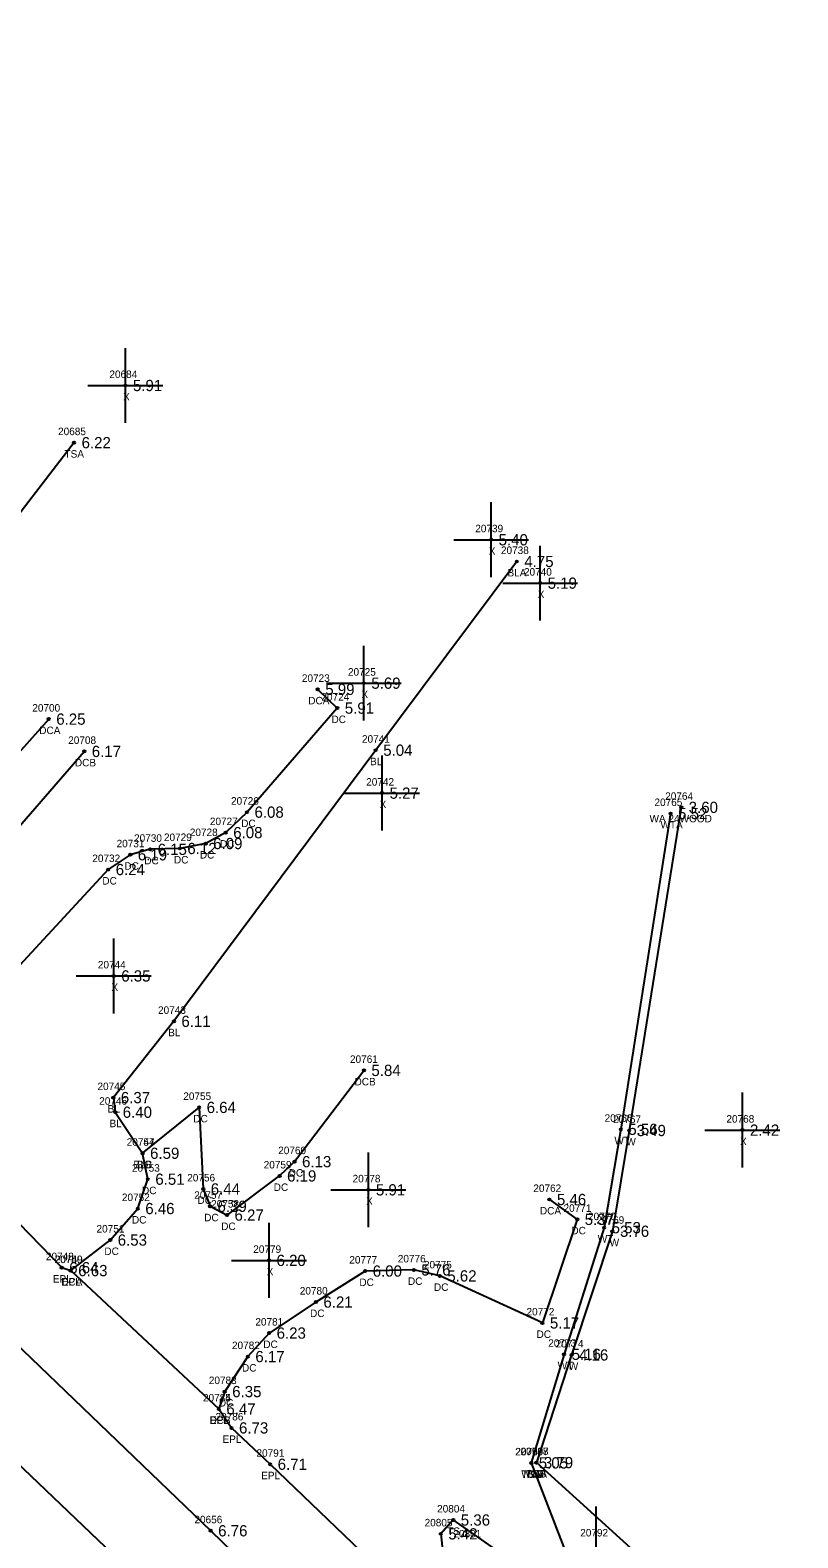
# Model space of a CAD drawing. Extents: x 2608745 to 2610333, y 641917 to 643463.
# Drawn here: x 2609231.6 to 2609334.1, y 642947.8 to 643149.1 of the extents above; entities that cross this region are included whole.
import ezdxf

# ---------------------------------------------------------------- set-up
doc = ezdxf.new("R2010")
doc.units = 0
for name, color, linetype in [('RD_DTM_BkLn1', 7, 'Continuous'), ('RD_DTM_BkLn2', 7, 'Continuous'), ('RD_DTM_BkLn_txCode', 7, 'Continuous'), ('RD_EX_BldgApp', 7, 'Continuous'), ('RD_EX_Conc', 7, 'Continuous'), ('RD_EX_Conc_txCode', 7, 'Continuous'), ('RD_EX_H2O_txCode', 7, 'Continuous'), ('RD_EX_Misc', 7, 'Continuous'), ('RD_EX_Misc_txCode', 7, 'Continuous'), ('RD_EX_Road', 7, 'Continuous'), ('RD_EX_Road_txCode', 7, 'Continuous'), ('RD_EX_TX_Conc_ELEV', 7, 'Continuous'), ('RD_EX_TX_Misc_ELEV', 7, 'Continuous'), ('RD_EX_TX_Road_ELEV', 7, 'Continuous'), ('RD_HC_Survey_ELEV', 7, 'Continuous'), ('RD_HC_Survey_txCode', 7, 'Continuous'), ('RD_SMD_Locator', 7, 'Continuous')]:
    doc.layers.add(name, color=color, linetype=linetype)

msp = doc.modelspace()

# ---------------------------------------------------------------- linework, layer by layer
at = {"layer": 'RD_DTM_BkLn1'}
for points in [[(2608814.73, 643373.65), (2608890.45, 643300.26), (2608962.19, 643231.31), (2609034.91, 643161.19), (2609108.48, 643089.9), (2609179.19, 643022.29), (2609255.71, 642948.78), (2609335.19, 642871.73), (2609410.7, 642798.48), (2609491.67, 642719.95), (2609518.07, 642695.15)], [(2609296.57, 643078.16), (2609277.74, 643052.97), (2609250.8, 643016.78), (2609242.72, 643006.6), (2609242.97, 643004.65), (2609246.62, 642999.17)]]:
    msp.add_lwpolyline(points, dxfattribs=at)
at = {"layer": 'RD_DTM_BkLn2'}
for points in [[(2609237.48, 643094.02), (2609220.03, 643071.4), (2609211.12, 643054.65), (2609205.92, 643044.31), (2609194.28, 643037.36), (2609184.97, 643038.02), (2609177.99, 643040.62)], [(2609317.09, 643044.52), (2609310.45, 643002.37), (2609308.22, 642989.24), (2609302.88, 642972.34), (2609298.5, 642957.84)], [(2609298.5, 642957.84), (2609303.58, 642944.57), (2609301.78, 642940.67), (2609288.09, 642950.22), (2609286.42, 642948.37), (2609286.98, 642943.32), (2609297.07, 642935.45), (2609305.3, 642928.41), (2609313.77, 642918.5), (2609346.23, 642882.3), (2609422.21, 642809.45), (2609480.56, 642755.4), (2609506.75, 642733.83), (2609516.79, 642724.84), (2609528.1, 642713.09), (2609531.25, 642709.73), (2609532.97, 642706.82)], [(2609299.18, 642957.88), (2609318.45, 642940.41), (2609325.58, 642932.79), (2609321.98, 642922.91), (2609316.71, 642922.45), (2609350.68, 642886.23), (2609426.26, 642812.92), (2609486.18, 642762.85), (2609511.6, 642739.79), (2609523.11, 642729.83), (2609533.96, 642717.19), (2609534.91, 642710.27), (2609532.97, 642706.82)]]:
    msp.add_lwpolyline(points, dxfattribs=at)
at = {"layer": 'RD_EX_BldgApp'}
msp.add_lwpolyline([(2609318.51, 643045.34), (2609311.56, 643002.21), (2609309.33, 642988.76), (2609303.87, 642972.25), (2609299.18, 642957.88)], dxfattribs=at)
at = {"layer": 'RD_EX_Conc'}
for points in [[(2609270, 643061.09), (2609272.61, 643058.59), (2609260.56, 643044.7), (2609257.72, 643041.97), (2609255.04, 643040.51), (2609251.59, 643039.85), (2609247.63, 643039.74), (2609244.98, 643039.01), (2609242.03, 643037.04), (2609225.85, 643019.54), (2609223.43, 643016.61), (2609221.42, 643012.89), (2609217.13, 643003.17)], [(2609234.1, 643057.12), (2609221.9, 643043.51), (2609220.45, 643040.99), (2609220.11, 643038.99), (2609221.07, 643037.37), (2609222.83, 643036.74), (2609224.97, 643037.31), (2609226.44, 643038.55), (2609238.84, 643052.81)], [(2609237.03, 642983.51), (2609242.3, 642987.59), (2609245.98, 642991.79), (2609247.32, 642995.71), (2609246.62, 642999.17), (2609254.17, 643005.29), (2609254.72, 642994.41), (2609255.62, 642992.09), (2609257.89, 642990.92), (2609264.9, 642996.14), (2609266.9, 642998.05), (2609276.16, 643010.23)], [(2609300.92, 642993), (2609304.63, 642990.35), (2609299.98, 642976.52), (2609286.29, 642982.8), (2609282.82, 642983.6), (2609276.33, 642983.45), (2609269.75, 642979.31), (2609263.51, 642975.17), (2609260.67, 642972.03), (2609257.58, 642967.36), (2609256.8, 642965.04)]]:
    msp.add_lwpolyline(points, dxfattribs=at)
at = {"layer": 'RD_EX_Misc'}
for p, q in [((2609244.33, 643096.65), (2609244.33, 643106.65)), ((2609239.33, 643101.65), (2609249.33, 643101.65)), ((2609293.14, 643076.06), (2609293.14, 643086.06)), ((2609288.14, 643081.06), (2609298.14, 643081.06)), ((2609299.68, 643070.27), (2609299.68, 643080.27)), ((2609294.68, 643075.27), (2609304.68, 643075.27)), ((2609276.15, 643056.92), (2609276.15, 643066.92)), ((2609271.15, 643061.92), (2609281.15, 643061.92)), ((2609278.58, 643042.24), (2609278.58, 643052.24)), ((2609273.58, 643047.24), (2609283.58, 643047.24)), ((2609242.77, 643017.84), (2609242.77, 643027.84)), ((2609237.77, 643022.84), (2609247.77, 643022.84)), ((2609326.68, 642997.26), (2609326.68, 643007.26)), ((2609321.68, 643002.26), (2609331.68, 643002.26)), ((2609276.76, 642989.29), (2609276.76, 642999.29)), ((2609271.76, 642994.29), (2609281.76, 642994.29)), ((2609263.5, 642979.87), (2609263.5, 642989.87)), ((2609258.5, 642984.87), (2609268.5, 642984.87)), ((2609307.15, 642942.02), (2609307.15, 642952.02))]:
    msp.add_line(p, q, dxfattribs=at)
at = {"layer": 'RD_EX_Road'}
for points in [[(2608806.89, 643364.99), (2608810.18, 643361.1), (2608820.75, 643351.25), (2608881.81, 643292.24), (2608917.83, 643257.49), (2608933.21, 643242.71), (2608954.07, 643222.83), (2609026.06, 643154.19), (2609039.6, 643139.96), (2609073.88, 643106.95), (2609100.48, 643081.89), (2609124.19, 643058.87), (2609171.61, 643013.71), (2609183.19, 643002.28), (2609197.91, 642988.37), (2609247.59, 642940.95), (2609328.02, 642863.6), (2609402.61, 642790.3), (2609474.23, 642720.69), (2609483.84, 642711.58), (2609495.78, 642699.92), (2609509.81, 642686.45)], [(2609058.51, 643155.46), (2609096.06, 643119.37), (2609116.51, 643099.11), (2609162.4, 643055.35), (2609177.21, 643041.34), (2609188.35, 643030.96), (2609199.91, 643019.76), (2609205.8, 643014.04), (2609217.13, 643003.17), (2609235.83, 642983.9), (2609237.03, 642983.51), (2609256.8, 642965.04), (2609258.49, 642962.51), (2609263.65, 642957.66), (2609344.71, 642879.89), (2609418.83, 642806.19), (2609500.61, 642728.46), (2609512.38, 642716.82), (2609526.19, 642703.5)]]:
    msp.add_lwpolyline(points, dxfattribs=at)
at = {"layer": 'RD_SMD_Locator'}
for centre in [(2609244.33, 643101.65), (2609237.48, 643094.02), (2609293.14, 643081.06), (2609296.57, 643078.16), (2609299.68, 643075.27), (2609276.15, 643061.92), (2609270, 643061.09), (2609234.1, 643057.12), (2609272.61, 643058.59), (2609238.84, 643052.81), (2609277.74, 643052.97), (2609278.58, 643047.24), (2609318.51, 643045.34), (2609260.56, 643044.7), (2609317.09, 643044.52), (2609257.72, 643041.97), (2609244.98, 643039.01), (2609247.63, 643039.74), (2609251.59, 643039.85), (2609255.04, 643040.51), (2609242.03, 643037.04), (2609242.77, 643022.84), (2609250.8, 643016.78), (2609276.16, 643010.23), (2609242.72, 643006.6), (2609254.17, 643005.29), (2609242.97, 643004.65), (2609310.45, 643002.37), (2609311.56, 643002.21), (2609326.68, 643002.26), (2609246.62, 642999.17), (2609246.62, 642999.17), (2609266.9, 642998.05), (2609247.32, 642995.71), (2609264.9, 642996.14), (2609254.72, 642994.41), (2609276.76, 642994.29), (2609300.92, 642993), (2609245.98, 642991.79), (2609255.62, 642992.09), (2609257.89, 642990.92), (2609304.63, 642990.35), (2609308.22, 642989.24), (2609309.33, 642988.76), (2609242.3, 642987.59), (2609263.5, 642984.87), (2609235.83, 642983.9), (2609237.03, 642983.51), (2609237.03, 642983.51), (2609276.33, 642983.45), (2609282.82, 642983.6), (2609286.29, 642982.8), (2609269.75, 642979.31), (2609263.51, 642975.17), (2609299.98, 642976.52), (2609260.67, 642972.03), (2609302.88, 642972.34), (2609303.87, 642972.25), (2609257.58, 642967.36), (2609256.8, 642965.04), (2609256.8, 642965.04), (2609258.49, 642962.51), (2609263.65, 642957.66), (2609298.5, 642957.84), (2609298.5, 642957.84), (2609299.18, 642957.88), (2609299.18, 642957.88), (2609255.71, 642948.78), (2609288.09, 642950.22), (2609286.42, 642948.37)]:
    msp.add_circle(centre, 0.15, dxfattribs=at)

# ---------------------------------------------------------------- texts
at = {"layer": 'RD_DTM_BkLn_txCode'}
for s, p in [('20685', (2609235.34, 643095.02)), ('TSA', (2609236.2, 643092.02)), ('20738', (2609294.45, 643079.16)), ('BLA', (2609295.32, 643076.16)), ('20741', (2609275.9, 643053.97)), ('BL', (2609276.98, 643050.97)), ('20743', (2609248.68, 643017.78)), ('BL', (2609250.04, 643014.78)), ('20745', (2609240.6, 643007.6)), ('20746', (2609240.83, 643005.65)), ('BL', (2609241.96, 643004.6)), ('BL', (2609242.21, 643002.65)), ('20747', (2609244.5, 643000.17)), ('BLB', (2609245.39, 642997.17)), ('20790', (2609296.34, 642958.84)), ('20788', (2609297.07, 642958.88)), ('TSA', (2609297.21, 642955.84)), ('BSA', (2609297.92, 642955.88)), ('20804', (2609285.93, 642951.22)), ('20805', (2609284.26, 642949.37)), ('TS', (2609287.29, 642948.22))]:
    msp.add_text(s, height=1, dxfattribs=at).set_placement(p)
at = {"layer": 'RD_EX_Conc_txCode'}
for s, p in [('20723', (2609267.88, 643062.09)), ('DCA', (2609268.73, 643059.09)), ('20724', (2609270.49, 643059.59)), ('20700', (2609231.9, 643058.12)), ('DC', (2609271.83, 643056.59)), ('DCA', (2609232.83, 643055.12)), ('20708', (2609236.69, 643053.81)), ('DCB', (2609237.59, 643050.81)), ('20726', (2609258.42, 643045.7)), ('20727', (2609255.6, 643042.97)), ('DC', (2609259.78, 643042.7)), ('20730', (2609245.48, 643040.74)), ('20729', (2609249.47, 643040.85)), ('20728', (2609252.92, 643041.51)), ('20731', (2609243.15, 643040.01)), ('DC', (2609254.26, 643038.51)), ('DC', (2609256.94, 643039.97)), ('20732', (2609239.91, 643038.04)), ('DC', (2609244.2, 643037.01)), ('DC', (2609246.85, 643037.74)), ('DC', (2609250.81, 643037.85)), ('DC', (2609241.25, 643035.04)), ('20761', (2609274.3, 643011.23)), ('DCB', (2609274.91, 643008.23)), ('20755', (2609252.05, 643006.29)), ('DC', (2609253.39, 643003.29)), ('20754', (2609244.5, 643000.17)), ('20760', (2609264.72, 642999.05)), ('20753', (2609245.2, 642996.71)), ('DC', (2609245.84, 642997.17)), ('20759', (2609262.78, 642997.14)), ('DC', (2609266.12, 642996.05)), ('20756', (2609252.58, 642995.41)), ('DC', (2609264.12, 642994.14)), ('20762', (2609298.77, 642994)), ('20752', (2609243.86, 642992.79)), ('DC', (2609246.54, 642993.71)), ('20757', (2609253.51, 642993.09)), ('DC', (2609253.94, 642992.41)), ('20758', (2609255.77, 642991.92)), ('DC', (2609254.84, 642990.09)), ('DCA', (2609299.65, 642991)), ('20771', (2609302.8, 642991.35)), ('20751', (2609240.47, 642988.59)), ('DC', (2609245.2, 642989.79)), ('DC', (2609257.11, 642988.92)), ('DC', (2609303.85, 642988.35)), ('20750', (2609234.87, 642984.51)), ('DC', (2609241.52, 642985.59)), ('20777', (2609274.21, 642984.45)), ('20776', (2609280.68, 642984.6)), ('20775', (2609284.17, 642983.8)), ('DCA', (2609235.76, 642981.51)), ('20780', (2609267.6, 642980.31)), ('DC', (2609275.55, 642981.45)), ('DC', (2609282.04, 642981.6)), ('DC', (2609285.51, 642980.8)), ('20781', (2609261.67, 642976.17)), ('DC', (2609268.97, 642977.31)), ('20772', (2609297.86, 642977.52)), ('DC', (2609299.2, 642974.52)), ('20782', (2609258.55, 642973.03)), ('DC', (2609262.73, 642973.17)), ('DC', (2609259.89, 642970.03)), ('20783', (2609255.46, 642968.36)), ('20784', (2609254.68, 642966.04)), ('DC', (2609256.8, 642965.36)), ('DCB', (2609255.55, 642963.04))]:
    msp.add_text(s, height=1, dxfattribs=at).set_placement(p)
at = {"layer": 'RD_EX_H2O_txCode'}
msp.add_text('20801', height=1, dxfattribs=at).set_placement((2609288.1, 642947.89))
at = {"layer": 'RD_EX_Misc_txCode'}
for s, p in [('20684', (2609242.19, 643102.65)), ('X', (2609244.02, 643099.65)), ('20739', (2609291.02, 643082.06)), ('X', (2609292.82, 643079.06)), ('20740', (2609297.52, 643076.27)), ('X', (2609299.36, 643073.27)), ('20725', (2609274.03, 643062.92)), ('X', (2609275.83, 643059.92)), ('20742', (2609276.46, 643048.24)), ('20764', (2609316.37, 643046.34)), ('X', (2609278.26, 643045.24)), ('20765', (2609314.94, 643045.52)), ('WA 24WOOD', (2609314.28, 643043.34)), ('WTA', (2609315.74, 643042.52)), ('20744', (2609240.65, 643023.84)), ('X', (2609242.46, 643020.84)), ('20766', (2609308.28, 643003.37)), ('20767', (2609309.42, 643003.21)), ('20768', (2609324.54, 643003.26)), ('WT', (2609309.59, 643000.37)), ('W', (2609311.19, 643000.21)), ('X', (2609326.36, 643000.26)), ('20778', (2609274.65, 642995.29)), ('X', (2609276.45, 642992.29)), ('20770', (2609306.07, 642990.24)), ('20769', (2609307.19, 642989.76)), ('20779', (2609261.39, 642985.87)), ('WT', (2609307.37, 642987.24)), ('W', (2609308.96, 642986.76)), ('X', (2609263.19, 642982.87)), ('20773', (2609300.76, 642973.34)), ('20774', (2609301.75, 642973.25)), ('WT', (2609302.02, 642970.34)), ('W', (2609303.5, 642970.25)), ('20789', (2609296.38, 642958.84)), ('20787', (2609297.07, 642958.88)), ('WTB', (2609297.16, 642955.84)), ('WB', (2609298.34, 642955.88)), ('20792', (2609305.03, 642948.02))]:
    msp.add_text(s, height=1, dxfattribs=at).set_placement(p)
at = {"layer": 'RD_EX_Road_txCode'}
for s, p in [('20748', (2609233.72, 642984.9)), ('20749', (2609234.91, 642984.51)), ('EPL', (2609234.63, 642981.9)), ('EPL', (2609235.83, 642981.51)), ('20785', (2609254.68, 642966.04)), ('EPL', (2609255.6, 642963.04)), ('20786', (2609256.35, 642963.51)), ('EPL', (2609257.29, 642960.51)), ('20791', (2609261.82, 642958.66)), ('EPL', (2609262.45, 642955.66))]:
    msp.add_text(s, height=1, dxfattribs=at).set_placement(p)
at = {"layer": 'RD_EX_TX_Conc_ELEV'}
for s, p in [('5.99', (2609271, 643060.34)), ('5.91', (2609273.61, 643057.84)), ('6.25', (2609235.1, 643056.37)), ('6.17', (2609239.84, 643052.06)), ('6.08', (2609261.56, 643043.95)), ('6.09', (2609256.04, 643039.76)), ('6.08', (2609258.72, 643041.22)), ('6.19', (2609245.98, 643038.26)), ('6.15', (2609248.63, 643038.99)), ('6.12', (2609252.59, 643039.1)), ('6.24', (2609243.03, 643036.29)), ('5.84', (2609277.16, 643009.48)), ('6.64', (2609255.17, 643004.54)), ('6.59', (2609247.62, 642998.42)), ('6.19', (2609265.9, 642995.39)), ('6.13', (2609267.9, 642997.3)), ('6.51', (2609248.32, 642994.96)), ('6.44', (2609255.72, 642993.66)), ('6.39', (2609256.62, 642991.34)), ('5.46', (2609301.92, 642992.25)), ('6.46', (2609246.98, 642991.04)), ('6.27', (2609258.89, 642990.17)), ('5.37', (2609305.63, 642989.6)), ('6.53', (2609243.3, 642986.84)), ('6.63', (2609238.03, 642982.76)), ('6.00', (2609277.33, 642982.7)), ('5.76', (2609283.82, 642982.85)), ('5.62', (2609287.29, 642982.05)), ('6.21', (2609270.75, 642978.56)), ('5.17', (2609300.98, 642975.77)), ('6.23', (2609264.51, 642974.42)), ('6.17', (2609261.67, 642971.28)), ('6.35', (2609258.58, 642966.61)), ('6.47', (2609257.8, 642964.29))]:
    msp.add_text(s, height=1.5, dxfattribs=at).set_placement(p)
at = {"layer": 'RD_EX_TX_Misc_ELEV'}
for s, p in [('5.91', (2609245.33, 643100.9)), ('6.22', (2609238.48, 643093.27)), ('5.40', (2609294.14, 643080.31)), ('4.75', (2609297.57, 643077.41)), ('5.19', (2609300.68, 643074.52)), ('5.69', (2609277.15, 643061.17)), ('5.04', (2609278.74, 643052.22)), ('5.27', (2609279.58, 643046.49)), ('5.52', (2609318.09, 643043.77)), ('3.60', (2609319.51, 643044.59)), ('6.35', (2609243.77, 643022.09)), ('6.11', (2609251.8, 643016.03)), ('6.37', (2609243.72, 643005.85)), ('6.40', (2609243.97, 643003.9)), ('5.56', (2609311.45, 643001.62)), ('3.49', (2609312.56, 643001.46)), ('2.42', (2609327.68, 643001.51)), ('6.59', (2609247.62, 642998.42)), ('5.91', (2609277.76, 642993.54)), ('5.53', (2609309.22, 642988.49)), ('3.76', (2609310.33, 642988.01)), ('6.20', (2609264.5, 642984.12)), ('5.16', (2609303.88, 642971.59)), ('4.16', (2609304.87, 642971.5)), ('3.79', (2609300.18, 642957.13)), ('3.79', (2609300.18, 642957.13)), ('5.05', (2609299.5, 642957.09)), ('5.05', (2609299.5, 642957.09)), ('5.36', (2609289.09, 642949.47)), ('5.42', (2609287.42, 642947.62))]:
    msp.add_text(s, height=1.5, dxfattribs=at).set_placement(p)
at = {"layer": 'RD_EX_TX_Road_ELEV'}
for s, p in [('6.64', (2609236.83, 642983.15)), ('6.63', (2609238.03, 642982.76)), ('6.47', (2609257.8, 642964.29)), ('6.73', (2609259.49, 642961.76)), ('6.71', (2609264.65, 642956.91))]:
    msp.add_text(s, height=1.5, dxfattribs=at).set_placement(p)
at = {"layer": 'RD_HC_Survey_ELEV'}
msp.add_text('6.76', height=1.5, dxfattribs=at).set_placement((2609256.71, 642948.03))
at = {"layer": 'RD_HC_Survey_txCode'}
msp.add_text('20656', height=1, dxfattribs=at).set_placement((2609253.54, 642949.78))

doc.saveas('drawing.dxf')
